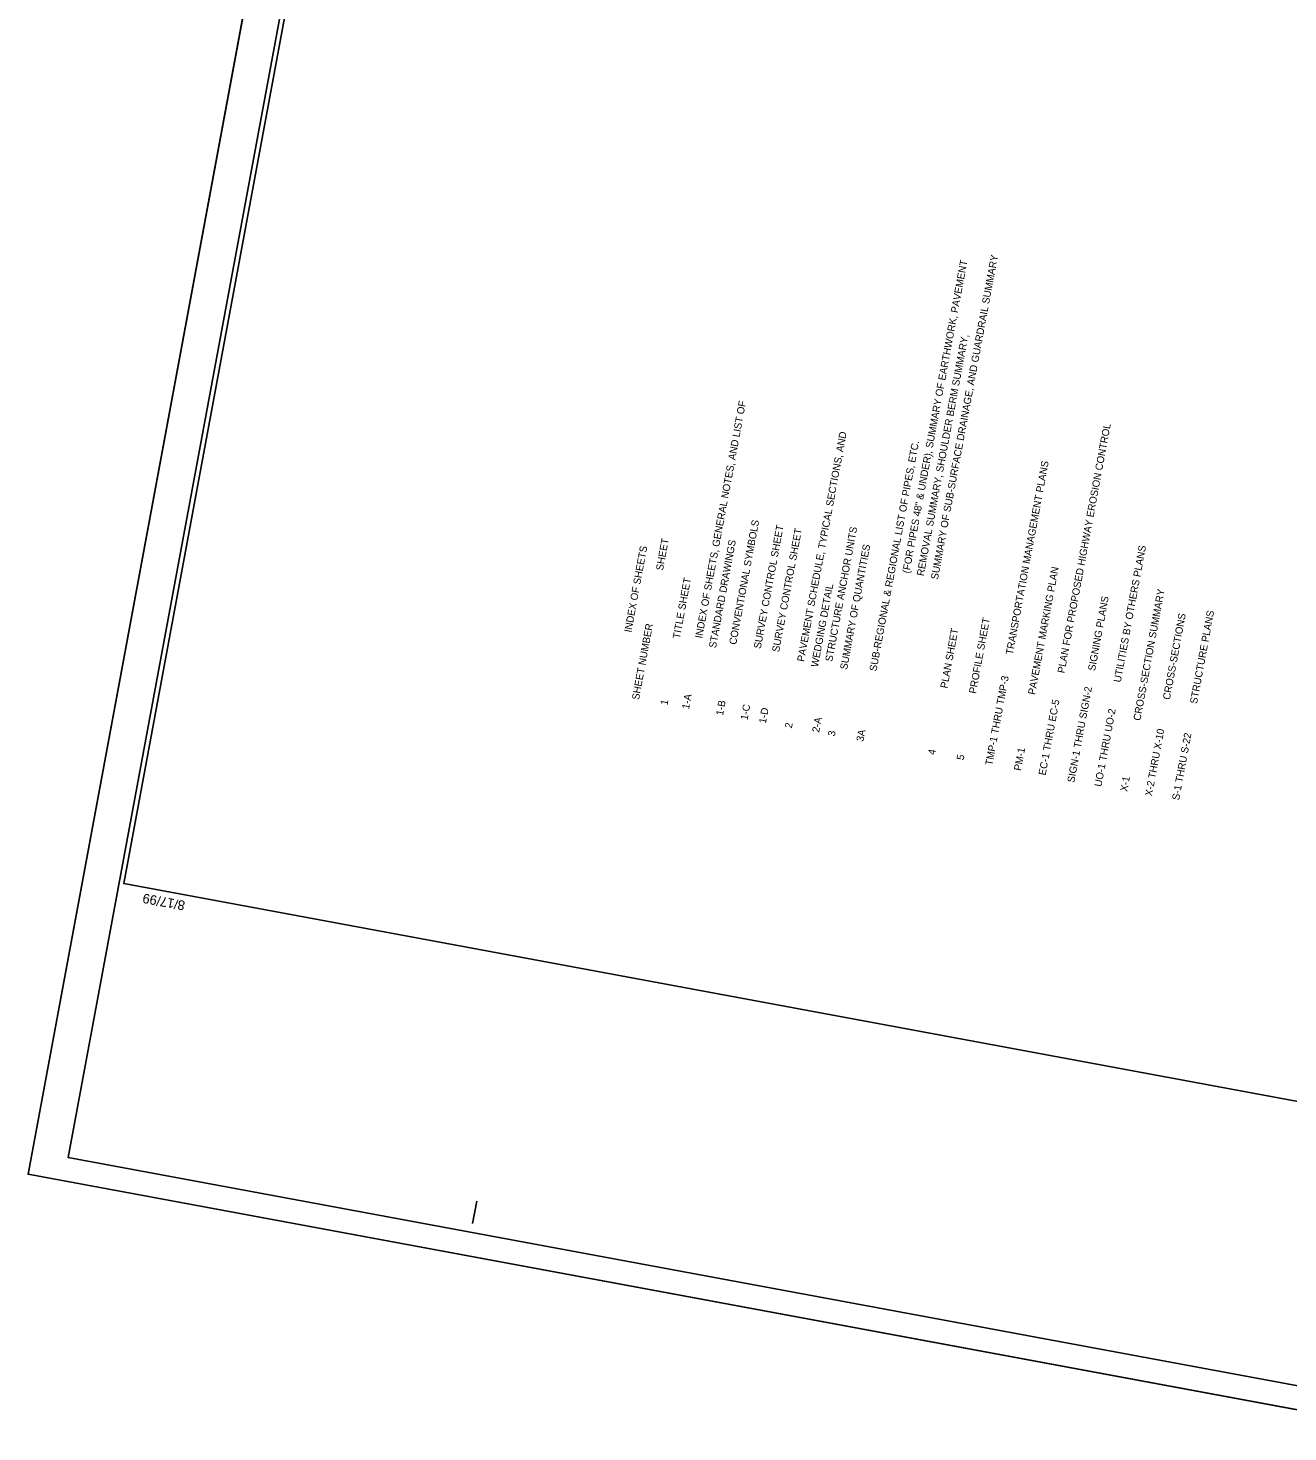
# Model space of a CAD drawing. Extents: x 1665923 to 1668724, y 690926 to 694920.
# Drawn here: x 1667341 to 1668033, y 693124 to 693895 of the extents above; entities that cross this region are included whole.
import ezdxf

# ---------------------------------------------------------------- set-up
doc = ezdxf.new("R2010")
doc.units = 0
for name, color, linetype in [('Sheet Cutting Line CELL', 7, 'Continuous'), ('Sheet Data Text CELL', 7, 'Continuous'), ('Sheet Plan CELL', 7, 'Continuous'), ('Sheet Plot Border Inside CELL', 7, 'Continuous'), ('Sheet Plot Border Outside CELL', 7, 'Continuous')]:
    doc.layers.add(name, color=color, linetype=linetype)

msp = doc.modelspace()

# ---------------------------------------------------------------- linework, layer by layer
at = {"layer": 'Sheet Cutting Line CELL'}
for p, q in [((1667647.87, 694920.43), (1667340.61, 693265.21)), ((1667340.61, 693265.21), (1668417.22, 693065.36))]:
    msp.add_line(p, q, dxfattribs=at)
at = {"layer": 'Sheet Plan CELL'}
for p, q in [((1667393.12, 693424.81), (1667393.12, 693424.81)), ((1667584.78, 693238.19), (1667587.06, 693250.48))]:
    msp.add_line(p, q, dxfattribs=at)
msp.add_lwpolyline([(1667666.89, 694899.61), (1667393.12, 693424.81), (1668425.49, 693233.17), (1668699.25, 694707.98)], close=True, dxfattribs=at)
at = {"layer": 'Sheet Plot Border Inside CELL'}
msp.add_lwpolyline([(1668399.93, 693081.79), (1668703.99, 694719.81), (1667666.71, 694912.36), (1667362.65, 693274.34)], close=True, dxfattribs=at)
at = {"layer": 'Sheet Plot Border Outside CELL'}
msp.add_lwpolyline([(1668417.22, 693065.36), (1668724.48, 694720.58), (1667647.87, 694920.43), (1667340.61, 693265.21)], close=True, dxfattribs=at)

# ---------------------------------------------------------------- texts
at = {"layer": 'Sheet Data Text CELL'}
for s, p in [('(FOR PIPES 48" & UNDER), SUMMARY OF EARTHWORK, PAVEMENT', (1667824.67, 693594.98)), ('SUMMARY OF SUB-SURFACE DRAINAGE, AND GUARDRAIL SUMMARY', (1667840.3, 693591.55)), ('REMOVAL SUMMARY, SHOULDER BERM SUMMARY,', (1667832.53, 693593.52)), ('1-A                     INDEX OF SHEETS, GENERAL NOTES, AND LIST OF ', (1667703.6, 693520.39)), ('2                       PAVEMENT SCHEDULE, TYPICAL SECTIONS, AND ', (1667760.06, 693509.91)), ('EC-1 THRU EC-5          PLAN FOR PROPOSED HIGHWAY EROSION CONTROL', (1667899.43, 693484.03)), ('3A                      SUB-REGIONAL & REGIONAL LIST OF PIPES, ETC. ', (1667799.38, 693502.6)), ('TMP-1 THRU TMP-3        TRANSPORTATION MANAGEMENT PLANS', (1667870.17, 693489.46)), ('1-B                     CONVENTIONAL SYMBOLS ', (1667722.27, 693516.92)), ('1-C                     SURVEY CONTROL SHEET ', (1667735.75, 693514.42)), ('1-D                     SURVEY CONTROL SHEET', (1667745.82, 693512.55)), ('2-A                     STRUCTURE ANCHOR UNITS', (1667775.07, 693507.61)), ('                        INDEX OF SHEETS ', (1667665.43, 693527.47)), ('SHEET NUMBER                    SHEET   ', (1667676.11, 693525.49)), ('                        STANDARD DRAWINGS', (1667711.89, 693518.85)), ('3                       SUMMARY OF QUANTITIES ', (1667783.65, 693505.53)), ('UO-1 THRU UO-2          UTILITIES BY OTHERS PLANS', (1667930.09, 693477.81)), ('PM-1                    PAVEMENT MARKING PLAN', (1667885.91, 693486.54)), ('1                       TITLE SHEET', (1667691.78, 693522.58)), ('                        WEDGING DETAIL ', (1667767.92, 693508.45)), ('X-1                     CROSS-SECTION SUMMARY', (1667944.28, 693475.17)), ('SIGN-1 THRU SIGN-2      SIGNING PLANS', (1667915.21, 693480.03)), ('5                       PROFILE SHEET  ', (1667854.44, 693492.38)), ('X-2 THRU X-10           CROSS-SECTIONS', (1667957.89, 693472.65)), ('S-1 THRU S-22           STRUCTURE PLANS', (1667972.77, 693470.42)), ('4                       PLAN SHEET', (1667838.71, 693495.3))]:
    msp.add_text(s, height=4, rotation=79.48395, dxfattribs=at).set_placement(p)
at = {"layer": 'Sheet Plan CELL'}
msp.add_text('8/17/99', height=5.25, rotation=169.48395, dxfattribs=at).set_placement((1667427.14, 693415.19))

doc.saveas('drawing.dxf')
